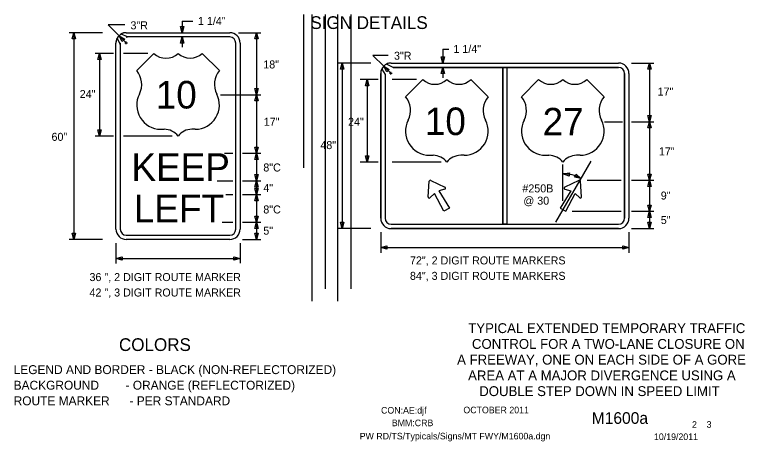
# Model space of a CAD drawing. Extents: x 16728 to 19508, y 5553 to 7079.
# Drawn here: x 17774 to 18463, y 5932 to 6334 of the extents above; entities that cross this region are included whole.
import ezdxf

# ---------------------------------------------------------------- set-up
doc = ezdxf.new("R2010")
doc.units = 0
for name, color, linetype in [('ALI_LEGAL_EX', 7, 'Continuous'), ('BORDER', 7, 'Continuous'), ('BORDER_SIGNAL_WO', 7, 'Continuous'), ('TRAFFIC_SIGNS_PR', 7, 'Continuous'), ('TYPICAL_EX', 7, 'Continuous'), ('TYPICAL_TEXT_DIMEN_PR', 7, 'Continuous')]:
    doc.layers.add(name, color=color, linetype=linetype)

msp = doc.modelspace()

# ---------------------------------------------------------------- linework, layer by layer
at = {"layer": 'ALI_LEGAL_EX'}
for p, q in [((18046.81, 6189.84), (18046.81, 6334.29)), ((18054.48, 6334.29), (18054.48, 6206.79)), ((18054.48, 6334.29), (18054.48, 6063.94)), ((18067.45, 6075.61), (18067.45, 6334.29)), ((18078.48, 6334.29), (18078.48, 6206.79)), ((18078.48, 6334.29), (18078.48, 6063.94)), ((18091.45, 6075.61), (18091.45, 6334.29))]:
    msp.add_line(p, q, dxfattribs=at)
at = {"layer": 'TRAFFIC_SIGNS_PR'}
for p, q in [((17879.58, 6317.25), (17977.08, 6317.25)), ((17872, 6313.63), (17870.99, 6312.12)), ((17871.02, 6312.05), (17873.89, 6306.01)), ((17880.78, 6313.18), (17874.69, 6315.93)), ((17977.08, 6313.18), (17879.58, 6313.18)), ((17869.83, 6132), (17869.83, 6307.5)), ((17873.89, 6307.5), (17873.89, 6132)), ((17982.77, 6132), (17982.77, 6307.5)), ((17986.83, 6307.5), (17986.83, 6132)), ((18120.27, 6282.81), (18123.41, 6277.76)), ((18131.06, 6284.5), (18124.82, 6287.51)), ((18129.1, 6288.55), (18343.6, 6288.55)), ((18129.1, 6288.55), (18343.6, 6288.55)), ((18131.04, 6284.49), (18234.32, 6284.49)), ((18343.6, 6284.49), (18131.04, 6284.49)), ((18234.32, 6284.49), (18234.32, 6136.61)), ((18238.38, 6284.49), (18238.38, 6136.61)), ((18238.38, 6284.49), (18343.6, 6284.49)), ((18119.35, 6278.8), (18119.35, 6142.3)), ((18119.35, 6142.3), (18119.35, 6278.8)), ((18123.41, 6277.75), (18123.41, 6142.3)), ((18123.41, 6277.75), (18123.41, 6142.3)), ((18349.29, 6278.8), (18349.29, 6233.05)), ((18349.29, 6142.3), (18349.29, 6278.8)), ((18353.35, 6278.8), (18353.35, 6142.3)), ((18353.35, 6278.8), (18353.35, 6142.3)), ((18349.29, 6233.05), (18349.29, 6142.3)), ((18163.95, 6162.41), (18165.1, 6177.12)), ((18166.62, 6177.99), (18179.93, 6171.63)), ((18306.08, 6177.99), (18292.77, 6171.63)), ((18308.75, 6162.41), (18307.6, 6177.12)), ((18129.1, 6136.61), (18343.6, 6136.61)), ((18129.1, 6132.55), (18343.6, 6132.55)), ((18343.6, 6132.55), (18129.1, 6132.55)), ((17879.58, 6126.31), (17977.08, 6126.31)), ((17977.08, 6122.25), (17879.58, 6122.25))]:
    msp.add_line(p, q, dxfattribs=at)
for points in [[(18131.04, 6284.49), (18131.03, 6284.49)], [(18123.41, 6277.76), (18123.41, 6277.75)], [(18179.77, 6169.66), (18174.04, 6168.09), (18184.26, 6151.92), (18178.86, 6148.8), (18169.97, 6165.74), (18165.74, 6161.57)], [(18292.93, 6169.66), (18298.66, 6168.09), (18288.44, 6151.92), (18293.84, 6148.8), (18302.73, 6165.74), (18306.96, 6161.57)]]:
    msp.add_lwpolyline(points, dxfattribs=at)
msp.add_lwpolyline([(18234.32, 6284.49), (18238.38, 6284.49), (18238.38, 6136.61), (18234.32, 6136.61)], close=True, dxfattribs=at)
for centre, radius, start, end in [((17879.58, 6307.5), 9.75, 90, 180), ((17878.99, 6309.67), 7.6, 85.58319, 124.53531), ((17977.08, 6307.5), 9.75, 0, 90), ((17876.86, 6308.09), 7.06, 145.86811, 184.82317), ((17880.18, 6317.61), 4.47, 262.2432, 277.7568), ((17977.08, 6307.5), 5.69, 0, 90), ((17868.43, 6306.75), 5.51, 352.24294, 7.75653), ((18125.48, 6279.5), 6.17, 147.60925, 186.56283), ((18129.1, 6278.8), 9.75, 90, 180), ((18129.1, 6278.8), 9.75, 90, 180), ((18128.42, 6281.98), 6.6, 84.11162, 123.06374), ((18130.04, 6291.67), 7.24, 277.81035, 278.05403), ((18343.6, 6278.8), 9.75, 0, 90), ((18343.6, 6278.8), 9.75, 0, 90), ((18343.6, 6278.8), 5.69, 0, 89.99421), ((18343.6, 6278.8), 5.69, 0, 90), ((18166.16, 6177.04), 1.06, 64.48226, 175.51774), ((18306.54, 6177.04), 1.06, 4.48226, 115.51774), ((18179.47, 6170.68), 1.06, 285.9885, 64.48226), ((18293.23, 6170.68), 1.06, 115.51774, 254.0115), ((18165.01, 6162.33), 1.06, 175.51775, 314.01151), ((18307.69, 6162.33), 1.06, 225.98849, 4.48225), ((18129.1, 6142.3), 9.75, 180, 270), ((18129.1, 6142.3), 9.75, 180, 270), ((18129.1, 6142.3), 5.69, 180, 270), ((18129.1, 6142.3), 5.69, 180, 270), ((18343.6, 6142.3), 9.75, 270, 0), ((18343.6, 6142.3), 5.69, 270, 0), ((18343.6, 6142.3), 9.75, 270, 0), ((18343.6, 6142.3), 5.69, 270, 0), ((17879.58, 6132), 9.75, 180, 270), ((17879.58, 6132), 5.69, 180, 270), ((17977.08, 6132), 5.69, 270, 0), ((17977.08, 6132), 9.75, 270, 0)]:
    msp.add_arc(centre, radius, start, end, dxfattribs=at)
at = {"layer": 'TYPICAL_EX'}
for p, q in [((17889.33, 6281.5), (17905.58, 6297.75)), ((17967.33, 6281.5), (17951.08, 6297.75)), ((18142.71, 6256.89), (18158.96, 6273.14)), ((18220.71, 6256.89), (18204.46, 6273.14)), ((18251.99, 6256.89), (18268.24, 6273.14)), ((18329.99, 6256.89), (18313.74, 6273.14)), ((17912.06, 6226.21), (17915.31, 6226.21)), ((17944.6, 6226.21), (17941.35, 6226.21)), ((18165.44, 6201.6), (18168.69, 6201.6)), ((18197.98, 6201.6), (18194.73, 6201.6)), ((18274.72, 6201.6), (18277.97, 6201.6)), ((18307.26, 6201.6), (18304.01, 6201.6))]:
    msp.add_line(p, q, dxfattribs=at)
for centre, radius, start, end in [((17916.95, 6309.58), 16.42, 226.14041, 313.85958), ((17939.7, 6309.59), 16.42, 226.14042, 313.85959), ((17873.93, 6268.49), 20.16, 333.09768, 40.19361), ((17982.73, 6268.49), 20.16, 139.80639, 206.90233), ((18170.34, 6284.97), 16.42, 226.14041, 313.85958), ((18193.09, 6284.97), 16.42, 226.14042, 313.85959), ((18279.62, 6284.97), 16.42, 226.14041, 313.85958), ((18302.36, 6284.97), 16.42, 226.14042, 313.85959), ((17912.1, 6248.93), 22.73, 152.6698, 269.90132), ((17944.56, 6248.93), 22.73, 270.09868, 27.3302), ((18127.31, 6243.88), 20.16, 333.09768, 40.19361), ((18236.11, 6243.88), 20.16, 139.80639, 206.90233), ((18236.59, 6243.88), 20.16, 333.09768, 40.19361), ((18345.39, 6243.88), 20.16, 139.80639, 206.90233), ((18165.48, 6224.32), 22.73, 152.6698, 269.90132), ((18197.94, 6224.32), 22.73, 270.09868, 27.3302), ((18274.76, 6224.32), 22.73, 152.6698, 269.90132), ((18307.22, 6224.32), 22.73, 270.09868, 27.3302), ((17915.35, 6209.93), 16.28, 37.1038, 90.13853), ((17941.31, 6209.93), 16.28, 89.86147, 142.8962), ((18168.73, 6185.32), 16.28, 37.1038, 90.13853), ((18194.69, 6185.32), 16.28, 89.86147, 142.8962), ((18278.01, 6185.32), 16.28, 37.1038, 90.13853), ((18303.97, 6185.32), 16.28, 89.86147, 142.8962)]:
    msp.add_arc(centre, radius, start, end, dxfattribs=at)
at = {"layer": 'TYPICAL_TEXT_DIMEN_PR'}
for p, q in [((17878.2, 6324.53), (17862.54, 6324.53)), ((17862.54, 6324.53), (17872.78, 6314.29)), ((17932.3, 6328.01), (17932.3, 6317.25)), ((17932.3, 6328.01), (17942.41, 6328.01)), ((17857, 6317.25), (17825.71, 6317.25)), ((17828.47, 6311.38), (17830.04, 6317.25)), ((17830.04, 6317.25), (17830.04, 6122.25)), ((17830.04, 6317.25), (17831.62, 6311.38)), ((17932.3, 6317.25), (17930.73, 6323.11)), ((17930.73, 6323.11), (17932.3, 6323.11)), ((17932.3, 6323.11), (17933.87, 6323.11)), ((17933.87, 6323.11), (17932.3, 6317.25)), ((17985.37, 6317.25), (18006.33, 6317.25)), ((18000.86, 6311.38), (18002.43, 6317.25)), ((18002.43, 6317.25), (18002.43, 6258.75)), ((18002.43, 6317.25), (18004, 6311.38)), ((17830.04, 6311.38), (17828.47, 6311.38)), ((17831.62, 6311.38), (17830.04, 6311.38)), ((17872.78, 6314.29), (17879.34, 6307.74)), ((17875.81, 6309.04), (17872.78, 6314.29)), ((17872.78, 6314.29), (17878.04, 6311.26)), ((17876.92, 6310.15), (17875.81, 6309.04)), ((17878.04, 6311.26), (17876.92, 6310.15)), ((17930.78, 6307.32), (17932.35, 6313.18)), ((17932.35, 6313.18), (17932.35, 6303.43)), ((17932.35, 6313.18), (17933.92, 6307.32)), ((18002.43, 6311.38), (18000.86, 6311.38)), ((18004, 6311.38), (18002.43, 6311.38)), ((17878.13, 6307.74), (17880.55, 6307.74)), ((17879.34, 6306.53), (17879.34, 6308.95)), ((17932.35, 6307.32), (17930.78, 6307.32)), ((17933.92, 6307.32), (17932.35, 6307.32)), ((17867.46, 6297.75), (17850.33, 6297.75)), ((17852.65, 6291.88), (17854.23, 6297.75)), ((17854.23, 6297.75), (17854.23, 6219.75)), ((17854.23, 6297.75), (17855.8, 6291.88)), ((17899.7, 6297.75), (17876.82, 6297.75)), ((18126.24, 6295.83), (18112.06, 6295.83)), ((18112.06, 6295.83), (18122.21, 6285.69)), ((18177.96, 6301.7), (18177.96, 6288.55)), ((18177.96, 6301.7), (18183.48, 6301.7)), ((17854.23, 6291.88), (17852.65, 6291.88)), ((17855.8, 6291.88), (17854.23, 6291.88)), ((18177.96, 6288.55), (18176.39, 6294.41)), ((18176.39, 6294.41), (18177.96, 6294.41)), ((18177.96, 6294.41), (18179.53, 6294.41)), ((18179.53, 6294.41), (18177.96, 6288.55)), ((18110.12, 6288.55), (18078.82, 6288.55)), ((18081.59, 6282.69), (18083.16, 6288.55)), ((18083.16, 6282.69), (18081.59, 6282.69)), ((18083.16, 6288.55), (18083.16, 6132.55)), ((18083.16, 6288.55), (18084.73, 6282.69)), ((18084.73, 6282.69), (18083.16, 6282.69)), ((18122.21, 6285.69), (18128.86, 6279.04)), ((18125.25, 6280.43), (18122.21, 6285.68)), ((18122.21, 6285.68), (18127.47, 6282.65)), ((18127.47, 6282.65), (18126.36, 6281.54)), ((18176.44, 6278.62), (18178.01, 6284.49)), ((18176.44, 6278.62), (18178.01, 6284.49)), ((18178.01, 6284.49), (18178.01, 6274.74)), ((18178.01, 6284.49), (18179.58, 6278.62)), ((18178.01, 6284.49), (18179.58, 6278.62)), ((18355.72, 6288.55), (18376.68, 6288.55)), ((18371.22, 6282.69), (18372.79, 6288.55)), ((18372.79, 6282.69), (18371.22, 6282.69)), ((18372.78, 6288.55), (18372.78, 6233.3)), ((18372.79, 6288.55), (18374.36, 6282.69)), ((18374.36, 6282.69), (18372.79, 6282.69)), ((18126.36, 6281.54), (18125.25, 6280.43)), ((18127.65, 6279.04), (18130.07, 6279.04)), ((18128.86, 6277.83), (18128.86, 6280.25)), ((18178.01, 6278.62), (18176.44, 6278.62)), ((18178.01, 6278.62), (18176.44, 6278.62)), ((18179.58, 6278.62), (18178.01, 6278.62)), ((18179.58, 6278.62), (18178.01, 6278.62)), ((18116.98, 6273.14), (18099.85, 6273.14)), ((18105.15, 6267.27), (18106.72, 6273.14)), ((18106.72, 6273.14), (18106.72, 6195.14)), ((18106.72, 6273.14), (18108.29, 6267.27)), ((18153.08, 6273.14), (18130.2, 6273.14)), ((18002.43, 6258.75), (18000.86, 6264.61)), ((18000.86, 6264.61), (18002.43, 6264.61)), ((18002.43, 6264.61), (18004, 6264.61)), ((18004, 6264.61), (18002.43, 6258.75)), ((18106.72, 6267.27), (18105.15, 6267.27)), ((18108.29, 6267.27), (18106.72, 6267.27)), ((17968.22, 6258.75), (18006.33, 6258.75)), ((18000.86, 6252.88), (18002.43, 6258.75)), ((18002.43, 6258.75), (18002.43, 6203.5)), ((18002.43, 6258.75), (18004, 6252.88)), ((18002.43, 6252.88), (18000.86, 6252.88)), ((18004, 6252.88), (18002.43, 6252.88)), ((18372.79, 6233.3), (18371.22, 6239.16)), ((18371.22, 6239.16), (18372.79, 6239.16)), ((18372.79, 6239.16), (18374.36, 6239.16)), ((18374.36, 6239.16), (18372.79, 6233.3)), ((18330.17, 6233.3), (18347.32, 6233.3)), ((18355.72, 6233.3), (18376.68, 6233.3)), ((18371.22, 6227.44), (18372.79, 6233.3)), ((18372.79, 6227.44), (18371.22, 6227.44)), ((18372.78, 6233.3), (18372.78, 6178.05)), ((18372.79, 6233.3), (18374.36, 6227.44)), ((18374.36, 6227.44), (18372.79, 6227.44)), ((17854.23, 6219.75), (17852.65, 6225.61)), ((17852.65, 6225.61), (17854.23, 6225.61)), ((17854.23, 6225.61), (17855.8, 6225.61)), ((17855.8, 6225.61), (17854.23, 6219.75)), ((17867.46, 6219.75), (17850.33, 6219.75)), ((17922.82, 6219.75), (17876.82, 6219.75)), ((18002.43, 6203.5), (18000.86, 6209.36)), ((18000.86, 6209.36), (18002.43, 6209.36)), ((18002.43, 6209.36), (18004, 6209.36)), ((18004, 6209.36), (18002.43, 6203.5)), ((17972.16, 6203.5), (17979.84, 6203.5)), ((17989.2, 6203.5), (18006.33, 6203.5)), ((18000.86, 6197.63), (18002.43, 6203.5)), ((18002.43, 6203.5), (18002.43, 6177.5)), ((18002.43, 6203.5), (18004, 6197.63)), ((18106.72, 6195.14), (18105.15, 6201)), ((18105.15, 6201), (18106.72, 6201)), ((18106.72, 6201), (18108.29, 6201)), ((18108.29, 6201), (18106.72, 6195.14)), ((18002.43, 6197.63), (18000.86, 6197.63)), ((18004, 6197.63), (18002.43, 6197.63)), ((18116.98, 6195.14), (18099.85, 6195.14)), ((18176.2, 6195.14), (18130.2, 6195.14)), ((18284.38, 6138.65), (18317.62, 6196.24)), ((18291.14, 6158.8), (18291.14, 6192.8)), ((18002.43, 6177.5), (18000.86, 6183.36)), ((18000.86, 6183.36), (18002.43, 6183.36)), ((18002.43, 6183.36), (18004, 6183.36)), ((18004, 6183.36), (18002.43, 6177.5)), ((18291.17, 6184.24), (18297.16, 6185.2)), ((18296.84, 6182.08), (18291.17, 6184.24)), ((18297, 6183.64), (18296.84, 6182.08)), ((18297.16, 6185.2), (18297, 6183.64)), ((18302.15, 6180.92), (18302.84, 6182.33)), ((18308.12, 6179.79), (18302.15, 6180.92)), ((18302.84, 6182.33), (18303.52, 6183.75)), ((18303.52, 6183.75), (18308.12, 6179.79)), ((18372.79, 6178.05), (18371.22, 6183.91)), ((18371.22, 6183.91), (18372.79, 6183.91)), ((18372.79, 6183.91), (18374.36, 6183.91)), ((18374.36, 6183.91), (18372.79, 6178.05)), ((17965.14, 6177.5), (17979.84, 6177.5)), ((17989.2, 6177.5), (18006.33, 6177.5)), ((18000.86, 6171.63), (18002.43, 6177.5)), ((18002.43, 6177.5), (18002.43, 6164.5)), ((18002.43, 6177.5), (18004, 6171.63)), ((18314.09, 6178.05), (18345.96, 6178.05)), ((18355.72, 6178.05), (18376.68, 6178.05)), ((18371.22, 6172.19), (18372.79, 6178.05)), ((18372.79, 6172.19), (18371.22, 6172.19)), ((18372.78, 6178.05), (18372.78, 6148.8)), ((18372.79, 6178.05), (18374.36, 6172.19)), ((18374.36, 6172.19), (18372.79, 6172.19)), ((18002.43, 6171.63), (18000.86, 6171.63)), ((18002.43, 6164.5), (18000.86, 6170.36)), ((18000.86, 6170.36), (18002.43, 6170.36)), ((18004, 6171.63), (18002.43, 6171.63)), ((18002.43, 6170.36), (18004, 6170.36)), ((18004, 6170.36), (18002.43, 6164.5)), ((17973.49, 6164.5), (17979.84, 6164.5)), ((17989.2, 6164.5), (18006.33, 6164.5)), ((18000.86, 6158.63), (18002.43, 6164.5)), ((18002.43, 6158.63), (18000.86, 6158.63)), ((18002.43, 6164.5), (18002.43, 6138.5)), ((18002.43, 6164.5), (18004, 6158.63)), ((18004, 6158.63), (18002.43, 6158.63)), ((18372.79, 6148.8), (18371.22, 6154.66)), ((18371.22, 6154.66), (18372.79, 6154.66)), ((18372.79, 6154.66), (18374.36, 6154.66)), ((18374.36, 6154.66), (18372.79, 6148.8)), ((18002.43, 6138.5), (18000.86, 6144.36)), ((18000.86, 6144.36), (18002.43, 6144.36)), ((18002.43, 6144.36), (18004, 6144.36)), ((18004, 6144.36), (18002.43, 6138.5)), ((18299.96, 6148.8), (18345.96, 6148.8)), ((18355.72, 6148.8), (18376.68, 6148.8)), ((18371.22, 6142.94), (18372.79, 6148.8)), ((18372.78, 6148.8), (18372.78, 6132.55)), ((18372.79, 6148.8), (18374.36, 6142.94)), ((17969.99, 6138.5), (17979.84, 6138.5)), ((17989.2, 6138.5), (18006.33, 6138.5)), ((18000.86, 6132.63), (18002.43, 6138.5)), ((18002.43, 6138.5), (18002.43, 6122.25)), ((18002.43, 6138.5), (18004, 6132.63)), ((18083.16, 6132.55), (18081.59, 6138.41)), ((18081.59, 6138.41), (18083.16, 6138.41)), ((18083.16, 6138.41), (18084.73, 6138.41)), ((18084.73, 6138.41), (18083.16, 6132.55)), ((18372.79, 6142.94), (18371.22, 6142.94)), ((18372.79, 6132.55), (18371.22, 6138.41)), ((18371.22, 6138.41), (18372.79, 6138.41)), ((18374.36, 6142.94), (18372.79, 6142.94)), ((18372.79, 6138.41), (18374.36, 6138.41)), ((18374.36, 6138.41), (18372.79, 6132.55)), ((18002.43, 6132.63), (18000.86, 6132.63)), ((18004, 6132.63), (18002.43, 6132.63)), ((18110.12, 6132.55), (18078.82, 6132.55)), ((18355.72, 6132.55), (18372.85, 6132.55)), ((18355.72, 6132.55), (18376.68, 6132.55)), ((18355.72, 6132.55), (18372.85, 6132.55)), ((17830.04, 6122.25), (17828.47, 6128.11)), ((17828.47, 6128.11), (17830.04, 6128.11)), ((17830.04, 6128.11), (17831.62, 6128.11)), ((17831.62, 6128.11), (17830.04, 6122.25)), ((18002.43, 6122.25), (18000.86, 6128.11)), ((18000.86, 6128.11), (18002.43, 6128.11)), ((18002.43, 6128.11), (18004, 6128.11)), ((18004, 6128.11), (18002.43, 6122.25)), ((18119.35, 6129.2), (18119.35, 6109.64)), ((18353.35, 6129.2), (18353.35, 6109.64)), ((17857, 6122.25), (17825.71, 6122.25)), ((17869.83, 6118.9), (17869.83, 6099.55)), ((17986.83, 6118.9), (17986.83, 6100.01)), ((17989.2, 6122.25), (18006.33, 6122.25)), ((18119.35, 6114.58), (18125.21, 6116.15)), ((18119.35, 6114.58), (18353.35, 6114.58)), ((18125.21, 6113.01), (18119.35, 6114.58)), ((18125.21, 6116.15), (18125.21, 6114.58)), ((18125.21, 6114.58), (18125.21, 6113.01)), ((18347.49, 6114.58), (18347.49, 6116.15)), ((18347.49, 6116.15), (18353.35, 6114.58)), ((18353.35, 6114.58), (18347.49, 6113.01)), ((18347.49, 6113.01), (18347.49, 6114.58)), ((17869.83, 6104.27), (17875.69, 6105.85)), ((17869.83, 6104.27), (17986.83, 6104.27)), ((17875.69, 6102.7), (17869.83, 6104.27)), ((17875.69, 6105.85), (17875.69, 6104.27)), ((17875.69, 6104.27), (17875.69, 6102.7)), ((17980.97, 6104.27), (17980.97, 6105.85)), ((17980.97, 6105.85), (17986.83, 6104.27)), ((17986.83, 6104.27), (17980.97, 6102.7)), ((17980.97, 6102.7), (17980.97, 6104.27))]:
    msp.add_line(p, q, dxfattribs=at)
msp.add_arc((18291.33, 6149.8), 34.39, 60.74521, 90.32117, dxfattribs=at)

# ---------------------------------------------------------------- texts
at = {"layer": 'BORDER'}
for s, p in [('TYPICAL EXTENDED TEMPORARY TRAFFIC', (18201.85, 6033.97)), ('CONTROL FOR A TWO-LANE CLOSURE ON', (18205.35, 6019.11)), ('A FREEWAY, ONE ON EACH SIDE OF A GORE', (18191.37, 6004.27)), ('AREA AT A MAJOR DIVERGENCE USING A', (18201.72, 5989.41)), ('DOUBLE STEP DOWN IN SPEED LIMIT', (18212.22, 5974.57))]:
    msp.add_text(s, height=9.3, dxfattribs=at).set_placement(p)
at = {"layer": 'BORDER_SIGNAL_WO'}
for s, height, p in [('CON:AE:djf  ', 6.2, (18119.69, 5958.06)), ('    OCTOBER 2011    ', 6.2, (18188.08, 5958.34)), ('    M1600a   ', 11, (18301.86, 5948.38)), ('BMM:CRB   ', 6.2, (18129.81, 5946.17)), (' 2    3 ', 6.2, (18410.45, 5944.7)), ('PW RD/TS/Typicals/Signs/MT FWY/M1600a.dgn      ', 6.2, (18099.55, 5933.71)), ('10/19/2011    ', 6.2, (18376.93, 5933.13))]:
    msp.add_text(s, height=height, dxfattribs=at).set_placement(p)
at = {"layer": 'TRAFFIC_SIGNS_PR'}
for s, p in [('10', (17907.3, 6245.75)), ('10', (18160.95, 6220.68)), ('27', (18271.96, 6220.32)), ('KEEP', (17884.43, 6177.5)), ('LEFT', (17886.67, 6138.5))]:
    msp.add_text(s, height=26, dxfattribs=at).set_placement(p)
at = {"layer": 'TYPICAL_TEXT_DIMEN_PR'}
for s, height, p in [('1 1/4"', 7.55, (17947.1, 6324.5)), ('SIGN DETAILS', 12, (18053.06, 6320.72)), ('3"R', 7.55, (17883.47, 6320.41)), ('1 1/4"', 7.55, (18187.89, 6298.12)), ('3"R', 7.55, (18131.88, 6291.75)), ('18"', 7.55, (18008.67, 6283.52)), ('24"', 7.55, (17835.67, 6255.63)), ('17"', 7.55, (18380.36, 6257.91)), ('17"', 7.55, (18009.13, 6229.47)), ('24"', 7.55, (18088.58, 6229.47)), ('60"', 7.55, (17809.07, 6215.26)), ('48"', 7.55, (18062.46, 6207.45)), ('17"', 7.55, (18381.56, 6201.55)), ('8"C', 7.55, (18008.71, 6186.35)), ('4" ', 7.55, (18008.71, 6167.09)), ('#250B', 7.55, (18252.91, 6166.64)), ('9"', 7.55, (18383.34, 6159.89)), ('@ 30', 7.55, (18253.86, 6155.09)), ('8"C', 7.55, (18008.71, 6146.77)), ('5"', 7.55, (18383.34, 6136.79)), ('5" ', 7.55, (18008.71, 6126.79)), ('72", 2 DIGIT ROUTE MARKERS', 7.55, (18146.93, 6098.71)), ('36 ", 2 DIGIT ROUTE MARKER', 7.55, (17844.88, 6083.01)), ('84", 3 DIGIT ROUTE MARKERS', 7.55, (18146.93, 6084.16)), ('42 ", 3 DIGIT ROUTE MARKER', 7.55, (17844.88, 6068.47)), ('COLORS', 12, (17872.65, 6017.08)), ('LEGEND AND BORDER - BLACK (NON-REFLECTORIZED)', 8.4, (17773.37, 5995.3)), ('BACKGROUND        - ORANGE (REFLECTORIZED)', 8.4, (17773.37, 5980.6)), ('ROUTE MARKER      - PER STANDARD', 8.4, (17773.37, 5965.9))]:
    msp.add_text(s, height=height, dxfattribs=at).set_placement(p)

doc.saveas('drawing.dxf')
